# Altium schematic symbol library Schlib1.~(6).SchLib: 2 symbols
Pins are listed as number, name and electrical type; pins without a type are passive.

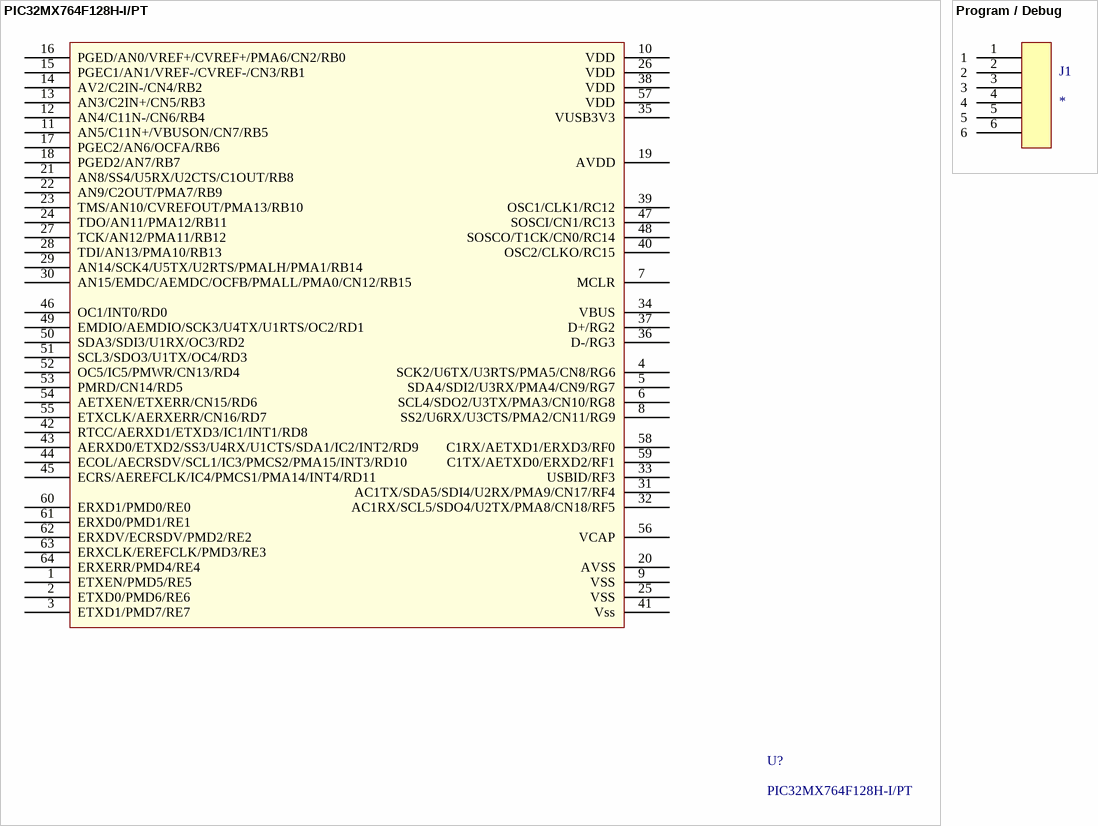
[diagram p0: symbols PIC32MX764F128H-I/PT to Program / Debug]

## PIC32MX764F128H-I/PT
designator U?
Fabricant: Microchip; Fournisseur: Farnell; RefFournisseur: 1971889
pins: 1 ETXEN/PMD5/RE5, 2 ETXD0/PMD6/RE6, 3 ETXD1/PMD7/RE7, 4 SCK2/U6TX/U3RTS/PMA5/CN8/RG6, 5 SDA4/SDI2/U3RX/PMA4/CN9/RG7, 6 SCL4/SDO2/U3TX/PMA3/CN10/RG8, 7 MCLR, 8 SS2/U6RX/U3CTS/PMA2/CN11/RG9, 9 VSS, 10 VDD, 11 AN5/C11N+/VBUSON/CN7/RB5, 12 AN4/C11N-/CN6/RB4, 13 AN3/C2IN+/CN5/RB3, 14 AV2/C2IN-/CN4/RB2, 15 PGEC1/AN1/VREF-/CVREF-/CN3/RB1, 16 PGED/AN0/VREF+/CVREF+/PMA6/CN2/RB0, 17 PGEC2/AN6/OCFA/RB6, 18 PGED2/AN7/RB7, 19 AVDD, 20 AVSS, 21 AN8/SS4/U5RX/U2CTS/C1OUT/RB8, 22 AN9/C2OUT/PMA7/RB9, 23 TMS/AN10/CVREFOUT/PMA13/RB10, 24 TDO/AN11/PMA12/RB11, 25 VSS, 26 VDD, 27 TCK/AN12/PMA11/RB12, 28 TDI/AN13/PMA10/RB13, 29 AN14/SCK4/U5TX/U2RTS/PMALH/PMA1/RB14, 30 AN15/EMDC/AEMDC/OCFB/PMALL/PMA0/CN12/RB15, 31 AC1TX/SDA5/SDI4/U2RX/PMA9/CN17/RF4, 32 AC1RX/SCL5/SDO4/U2TX/PMA8/CN18/RF5, 33 USBID/RF3, 34 VBUS, 35 VUSB3V3, 36 D-/RG3, 37 D+/RG2, 38 VDD, 39 OSC1/CLK1/RC12, 40 OSC2/CLKO/RC15, 41 Vss, 42 RTCC/AERXD1/ETXD3/IC1/INT1/RD8, 43 AERXD0/ETXD2/SS3/U4RX/U1CTS/SDA1/IC2/INT2/RD9, 44 ECOL/AECRSDV/SCL1/IC3/PMCS2/PMA15/INT3/RD10, 45 ECRS/AEREFCLK/IC4/PMCS1/PMA14/INT4/RD11, 46 OC1/INT0/RD0, 47 SOSCI/CN1/RC13, 48 SOSCO/T1CK/CN0/RC14, 49 EMDIO/AEMDIO/SCK3/U4TX/U1RTS/OC2/RD1, 50 SDA3/SDI3/U1RX/OC3/RD2, 51 SCL3/SDO3/U1TX/OC4/RD3, 52 OC5/IC5/PMWR/CN13/RD4, 53 PMRD/CN14/RD5, 54 AETXEN/ETXERR/CN15/RD6, 55 ETXCLK/AERXERR/CN16/RD7, 56 VCAP, 57 VDD, 58 C1RX/AETXD1/ERXD3/RF0, 59 C1TX/AETXD0/ERXD2/RF1, 60 ERXD1/PMD0/RE0, 61 ERXD0/PMD1/RE1, 62 ERXDV/ECRSDV/PMD2/RE2, 63 ERXCLK/EREFCLK/PMD3/RE3, 64 ERXERR/PMD4/RE4

## Program / Debug
designator J1
Fournisseur: Farnell; Fabricant: Molex; Ref.Fournisseur: 1125368; Ref.Fabricant: 53398-0671
pins: 1, 2, 3, 4, 5, 6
